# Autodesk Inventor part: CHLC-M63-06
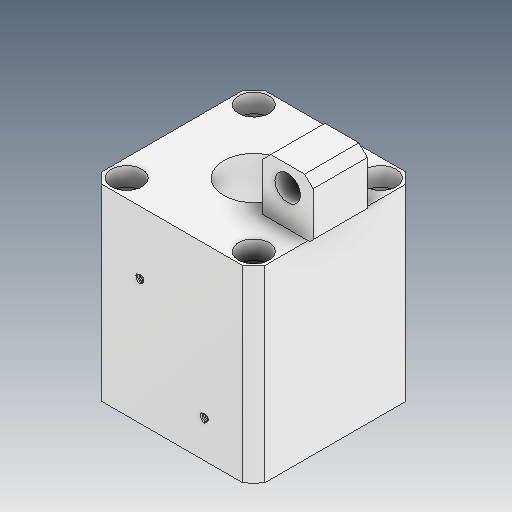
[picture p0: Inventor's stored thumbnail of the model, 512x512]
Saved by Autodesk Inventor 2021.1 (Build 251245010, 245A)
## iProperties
Created: 2021-05
Part Number: CHLC-M63-06
Material: Ogólny
Document SubType Name: Modeling
Designer: user
Density: 1 g/cm^3
Appearance: Domyślna
Author: user
Revision Number: ÈÎºÎ
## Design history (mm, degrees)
feature "ÊäÈë1"
node "Bryła1"
